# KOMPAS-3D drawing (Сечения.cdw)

Views: Спереди 1, Разрез А-А, Разрез Б-Б, Вид по стрелке 6, Вид 7, Вид 8
Referenced files: Сечения.cdw
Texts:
  Сечения
Dimensions and other numbers on the sheet: 6; 20; 28; 10; 17; 100; 8; 32; 36; 18; 1:1; 1; 0; 2; 3; 4; 5; 7; 9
